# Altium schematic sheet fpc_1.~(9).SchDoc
size A; SheetNumber: 1; SheetTotal: 2
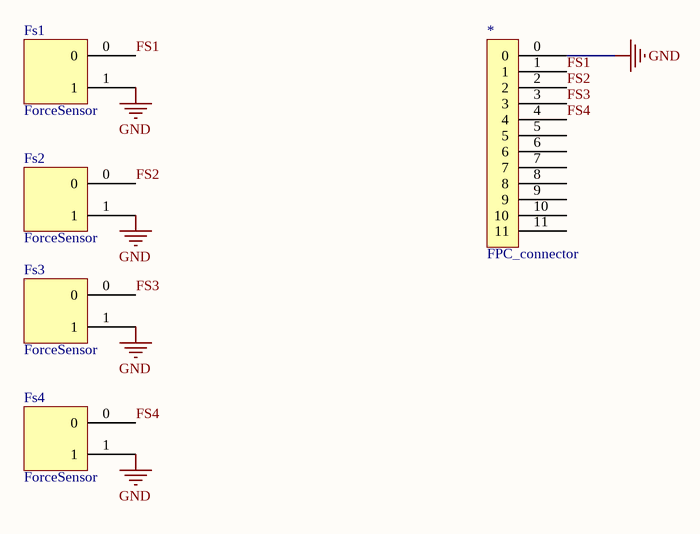
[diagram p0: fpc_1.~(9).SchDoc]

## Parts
*  FPC_connector  [FPC_connector]
Fs1  ForceSensor  [sensor_connector]
Fs2  ForceSensor  [sensor_connector]
Fs3  ForceSensor  [sensor_connector]
Fs4  ForceSensor  [sensor_connector]

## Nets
GND: *.0 Fs1.1 Fs2.1 Fs3.1 Fs4.1
FS1: *.1 Fs1.0
FS2: *.2 Fs2.0
FS3: *.3 Fs3.0
FS4: *.4 Fs4.0

Not connected (* = marked no-connect by the designer): * 5 6 7 8 9 10 11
